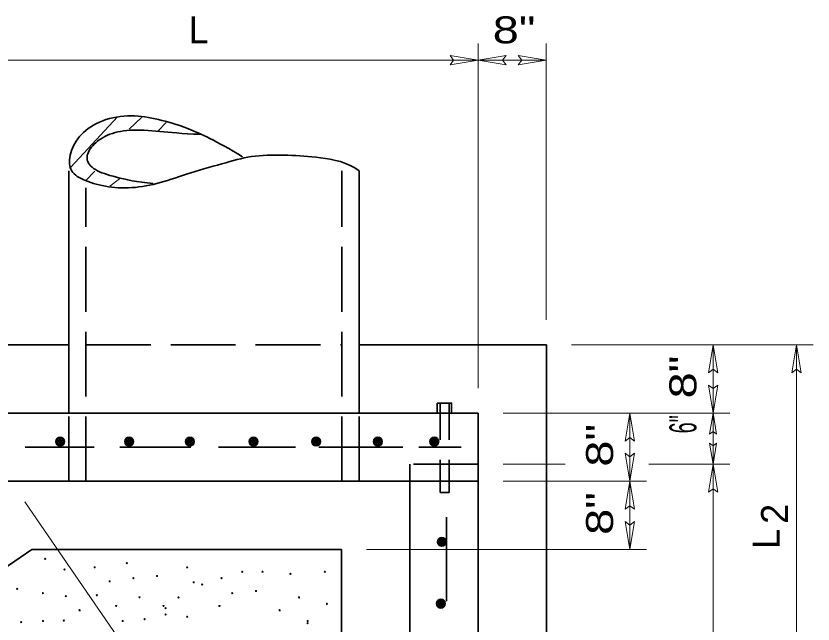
# Model space of a CAD drawing. Extents: x 178962.5 to 178977.5, y 178951.2 to 178972.9.
# Drawn here: x 178973.406 to 178977.392, y 178969.79 to 178972.831 of the extents above; entities that cross this region are included whole.
import ezdxf
from ezdxf.enums import TextEntityAlignment as Align

# ---------------------------------------------------------------- set-up
doc = ezdxf.new("R2010")
doc.units = 0
doc.header["$LTSCALE"] = 0.054
doc.linetypes.add('LONG_DASHED', pattern=[7.5, 6, -1.5])
doc.linetypes.add('MEDIUM_DASHED', pattern=[4.5, 3, -1.5])
for name, color, linetype, lineweight in [('1', 7, 'Continuous', 35), ('10', 7, 'Continuous', 13), ('12', 7, 'Continuous', 53), ('6', 7, 'Continuous', 13)]:
    doc.layers.add(name, color=color, linetype=linetype, lineweight=lineweight)

msp = doc.modelspace()

# ---------------------------------------------------------------- linework, layer by layer
at = {"layer": '1'}
for p, q in [((178973.67117, 178972.056), (178973.67117, 178970.8455)), ((178975.12183, 178972.056), (178975.12183, 178970.8455)), ((178972.56175, 178971.18683), (178973.67117, 178971.18683)), ((178976.05942, 178971.18683), (178975.12183, 178971.18683)), ((178976.05883, 178971.18683), (178976.05883, 178967.7735)), ((178975.51317, 178970.89517), (178975.51317, 178970.8455)), ((178975.528, 178970.8455), (178975.528, 178970.89517)), ((178975.57192, 178970.8455), (178975.57192, 178970.89517)), ((178975.7175, 178970.8455), (178972.9015, 178970.8455)), ((178975.7175, 178970.8455), (178975.7175, 178967.9015)), ((178973.63217, 178970.72417), (178973.60583, 178970.7005)), ((178973.62433, 178970.72442), (178973.60633, 178970.70842)), ((178973.638, 178970.72192), (178973.60725, 178970.6945)), ((178973.6425, 178970.71867), (178973.61008, 178970.68967)), ((178973.64592, 178970.71442), (178973.61383, 178970.68575)), ((178973.64833, 178970.70925), (178973.61875, 178970.68283)), ((178973.64933, 178970.70283), (178973.625, 178970.68117)), ((178973.64742, 178970.69375), (178973.63425, 178970.682)), ((178973.97683, 178970.72417), (178973.95033, 178970.7005)), ((178973.96892, 178970.72442), (178973.951, 178970.70842)), ((178973.98258, 178970.72192), (178973.95183, 178970.69458)), ((178973.98708, 178970.71875), (178973.95458, 178970.68975)), ((178973.99058, 178970.71442), (178973.9585, 178970.68575)), ((178973.993, 178970.70933), (178973.96342, 178970.68275)), ((178973.99392, 178970.70283), (178973.96958, 178970.68108)), ((178973.992, 178970.69375), (178973.97883, 178970.68208)), ((178974.28125, 178970.72417), (178974.25483, 178970.7005)), ((178974.27333, 178970.72442), (178974.25542, 178970.70842)), ((178974.287, 178970.72192), (178974.25625, 178970.69458)), ((178974.2915, 178970.71875), (178974.25908, 178970.68975)), ((178974.29492, 178970.71442), (178974.26283, 178970.68575)), ((178974.29733, 178970.70933), (178974.26775, 178970.68275)), ((178974.29833, 178970.70283), (178974.274, 178970.68108)), ((178974.29642, 178970.69375), (178974.28325, 178970.68208)), ((178974.59892, 178970.72417), (178974.5725, 178970.7005)), ((178974.59108, 178970.72442), (178974.57308, 178970.70842)), ((178974.60475, 178970.72192), (178974.574, 178970.69458)), ((178974.60917, 178970.71875), (178974.57675, 178970.68975)), ((178974.61275, 178970.71442), (178974.5805, 178970.68575)), ((178974.61517, 178970.70933), (178974.5855, 178970.68275)), ((178974.61608, 178970.70283), (178974.59175, 178970.68108)), ((178974.61417, 178970.69375), (178974.601, 178970.68208)), ((178974.91225, 178970.72417), (178974.88583, 178970.7005)), ((178974.90442, 178970.72442), (178974.8865, 178970.70842)), ((178974.91808, 178970.72192), (178974.88733, 178970.69458)), ((178974.9225, 178970.71875), (178974.89008, 178970.68975)), ((178974.92608, 178970.71442), (178974.89392, 178970.68575)), ((178974.9285, 178970.70933), (178974.89883, 178970.68275)), ((178974.92942, 178970.70283), (178974.90508, 178970.68108)), ((178974.9275, 178970.69375), (178974.91433, 178970.68208)), ((178975.22117, 178970.72417), (178975.19467, 178970.7005)), ((178975.21325, 178970.72442), (178975.19525, 178970.70842)), ((178975.22683, 178970.72192), (178975.19617, 178970.6945)), ((178975.23142, 178970.71867), (178975.19892, 178970.68967)), ((178975.23483, 178970.71442), (178975.20275, 178970.68575)), ((178975.23725, 178970.70925), (178975.20767, 178970.68283)), ((178975.23825, 178970.70283), (178975.21392, 178970.68117)), ((178975.23633, 178970.69375), (178975.22317, 178970.682)), ((178975.50308, 178970.72417), (178975.47658, 178970.7005)), ((178975.49525, 178970.72433), (178975.47725, 178970.70833)), ((178975.50892, 178970.722), (178975.47808, 178970.69458)), ((178975.51325, 178970.71867), (178975.48092, 178970.68967)), ((178975.51692, 178970.71442), (178975.48475, 178970.68575)), ((178975.51925, 178970.70933), (178975.48958, 178970.68275)), ((178975.52025, 178970.70283), (178975.49592, 178970.68117)), ((178975.51825, 178970.69375), (178975.50525, 178970.682)), ((178973.45217, 178970.67483), (178973.79675, 178970.67483)), ((178973.92658, 178970.67483), (178974.28017, 178970.67483)), ((178974.41883, 178970.67483), (178974.80383, 178970.67483)), ((178974.92017, 178970.67483), (178975.34083, 178970.67483)), ((178975.63217, 178970.67483), (178975.4215, 178970.67483)), ((178975.7175, 178970.50417), (178972.9015, 178970.50417)), ((178973.4135, 178970.50417), (178975.67483, 178970.50417)), ((178973.4135, 178970.50417), (178975.67483, 178970.50417)), ((178975.37617, 178970.50417), (178975.37617, 178967.9015)), ((178975.55917, 178969.90492), (178975.55917, 178970.32558)), ((178975.51983, 178970.21608), (178975.54883, 178970.18375)), ((178975.52408, 178970.21958), (178975.55275, 178970.18742)), ((178975.52917, 178970.222), (178975.55567, 178970.19242)), ((178975.53567, 178970.22292), (178975.55742, 178970.19867)), ((178975.54475, 178970.22108), (178975.5565, 178970.20792)), ((178975.51408, 178970.198), (178975.53008, 178970.18)), ((178975.51433, 178970.20583), (178975.538, 178970.17942)), ((178975.5165, 178970.21167), (178975.54392, 178970.18092)), ((178973.48525, 178970.16283), (178971.51783, 178968.81042)), ((178975.03483, 178970.16283), (178973.48525, 178970.16283)), ((178975.03483, 178970.16283), (178975.03483, 178967.7735)), ((178975.50983, 178969.89708), (178975.5335, 178969.87058)), ((178975.51217, 178969.90275), (178975.5395, 178969.87208)), ((178975.51542, 178969.90725), (178975.54442, 178969.87483)), ((178975.51967, 178969.91075), (178975.54825, 178969.87867)), ((178975.52475, 178969.91317), (178975.55125, 178969.8835)), ((178975.53117, 178969.91408), (178975.55292, 178969.88983)), ((178975.54025, 178969.91225), (178975.55208, 178969.89908)), ((178975.50967, 178969.88908), (178975.52567, 178969.87117))]:
    msp.add_line(p, q, dxfattribs=at)
at = {"layer": '1', "linetype": 'LONG_DASHED'}
for p, q in [((178975.0365, 178970.50417), (178975.0365, 178972.056)), ((178973.7565, 178970.50417), (178973.7565, 178971.97108)), ((178973.7565, 178971.18683), (178975.0365, 178971.18683)), ((178973.67117, 178970.50417), (178973.67117, 178970.8455)), ((178975.12183, 178970.50417), (178975.12183, 178970.8455)), ((178975.37617, 178970.5895), (178975.37617, 178970.50417)), ((178975.7175, 178970.5895), (178975.37617, 178970.5895))]:
    msp.add_line(p, q, dxfattribs=at)
at = {"layer": '1', "linetype": 'MEDIUM_DASHED'}
for p, q in [((178975.528, 178970.44883), (178975.528, 178970.8455)), ((178975.57192, 178970.44883), (178975.57192, 178970.8455)), ((178975.528, 178970.44883), (178975.57192, 178970.44883))]:
    msp.add_line(p, q, dxfattribs=at)
at = {"layer": '1'}
msp.add_lwpolyline([(178975.51317, 178970.89517), (178975.58492, 178970.89517), (178975.58492, 178970.8455)], dxfattribs=at)
for centre in [(178973.6275, 178970.70282), (178973.97208, 178970.70282), (178974.2765, 178970.70282), (178974.59425, 178970.70282), (178974.90758, 178970.70282), (178975.2164, 178970.70282), (178975.49838, 178970.70282), (178975.53569, 178970.20113), (178975.53125, 178969.89231)]:
    msp.add_circle(centre, 0.02184, dxfattribs=at)
for points in [[(178975.12183, 178972.056), (178975.06792, 178972.1005), (178974.91567, 178972.12733), (178974.7725, 178972.13625), (178974.5935, 178972.13625), (178974.46817, 178972.1005), (178974.27117, 178972.04708), (178974.128, 178971.9935), (178973.98475, 178971.96675), (178973.8505, 178971.97575), (178973.73408, 178972.01133), (178973.67117, 178972.056), (178973.6715, 178972.14508), (178973.72517, 178972.24317), (178973.83258, 178972.31458), (178973.98475, 178972.34133), (178974.11908, 178972.31458), (178974.25325, 178972.27892), (178974.4055, 178972.20758), (178974.53983, 178972.12733)], [(178974.0925, 178971.99375), (178974.01142, 178972.00025), (178973.89775, 178972.02608), (178973.79383, 178972.05842), (178973.74833, 178972.11675), (178973.78408, 178972.18458), (178973.85883, 178972.23958), (178973.96917, 178972.2655), (178974.125, 178972.25575), (178974.23217, 178972.24283), (178974.32958, 178972.23958)]]:
    msp.add_open_spline(points, degree=3, dxfattribs=at)
at = {"layer": '10'}
for p, q in [((178975.7175, 178972.69442), (178975.7175, 178970.9705)), ((178976.05842, 178972.69442), (178976.05842, 178971.31183)), ((178975.5775, 178972.63442), (178975.7175, 178972.61108)), ((178975.5775, 178972.63442), (178975.595, 178972.61108)), ((178975.5775, 178972.58775), (178975.7175, 178972.61108)), ((178975.5775, 178972.58775), (178975.595, 178972.61108)), ((178975.8575, 178972.63442), (178975.7175, 178972.61108)), ((178976.05842, 178972.61108), (178975.7175, 178972.61108)), ((178975.8575, 178972.58775), (178975.7175, 178972.61108)), ((178975.8575, 178972.63442), (178975.84, 178972.61108)), ((178975.8575, 178972.58775), (178975.84, 178972.61108)), ((178975.91842, 178972.63442), (178976.05842, 178972.61108)), ((178975.91842, 178972.63442), (178975.93592, 178972.61108)), ((178975.91842, 178972.58775), (178976.05842, 178972.61108)), ((178975.91842, 178972.58775), (178975.93592, 178972.61108)), ((178976.18442, 178971.18683), (178977.39233, 178971.18683)), ((178976.869, 178971.04683), (178976.89233, 178971.18683)), ((178976.89233, 178971.18683), (178976.89233, 178970.8455)), ((178976.91567, 178971.04683), (178976.89233, 178971.18683)), ((178977.28567, 178971.04683), (178977.309, 178971.18683)), ((178977.309, 178971.18683), (178977.309, 178969.39308)), ((178977.33233, 178971.04683), (178977.309, 178971.18683)), ((178976.869, 178971.04683), (178976.89233, 178971.06433)), ((178976.91567, 178971.04683), (178976.89233, 178971.06433)), ((178977.28567, 178971.04683), (178977.309, 178971.06433)), ((178977.33233, 178971.04683), (178977.309, 178971.06433)), ((178976.869, 178970.9855), (178976.89233, 178970.8455)), ((178976.869, 178970.9855), (178976.89233, 178970.968)), ((178976.91567, 178970.9855), (178976.89233, 178970.8455)), ((178976.91567, 178970.9855), (178976.89233, 178970.968)), ((178976.97567, 178970.8455), (178975.8425, 178970.8455)), ((178976.45233, 178970.7055), (178976.47567, 178970.8455)), ((178976.47567, 178970.8455), (178976.47567, 178970.50417)), ((178976.499, 178970.7055), (178976.47567, 178970.8455)), ((178976.87483, 178970.7405), (178976.89233, 178970.8455)), ((178976.89233, 178970.8455), (178976.89233, 178970.5895)), ((178976.90983, 178970.7405), (178976.89233, 178970.8455)), ((178976.87483, 178970.7405), (178976.89233, 178970.75367)), ((178976.90983, 178970.7405), (178976.89233, 178970.75367)), ((178976.45233, 178970.7055), (178976.47567, 178970.723)), ((178976.499, 178970.7055), (178976.47567, 178970.723)), ((178976.87483, 178970.6945), (178976.89233, 178970.5895)), ((178976.87483, 178970.6945), (178976.89233, 178970.68133)), ((178976.90983, 178970.6945), (178976.89233, 178970.5895)), ((178976.90983, 178970.6945), (178976.89233, 178970.68133)), ((178976.45233, 178970.64417), (178976.47567, 178970.50417)), ((178976.45233, 178970.64417), (178976.47567, 178970.62667)), ((178976.499, 178970.64417), (178976.47567, 178970.50417)), ((178976.499, 178970.64417), (178976.47567, 178970.62667)), ((178975.8425, 178970.5895), (178976.15225, 178970.5895)), ((178976.57067, 178970.5895), (178976.97567, 178970.5895)), ((178976.869, 178970.4495), (178976.89233, 178970.5895)), ((178976.89233, 178967.7735), (178976.89233, 178970.5895)), ((178976.91567, 178970.4495), (178976.89233, 178970.5895)), ((178975.8425, 178970.50417), (178976.559, 178970.50417)), ((178976.45233, 178970.36417), (178976.47567, 178970.50417)), ((178976.47567, 178970.50417), (178976.47567, 178970.16283)), ((178976.499, 178970.36417), (178976.47567, 178970.50417)), ((178976.869, 178970.4495), (178976.89233, 178970.467)), ((178976.91567, 178970.4495), (178976.89233, 178970.467)), ((178973.45008, 178970.40117), (178974.35142, 178969.09)), ((178976.45233, 178970.36417), (178976.47567, 178970.38167)), ((178976.499, 178970.36417), (178976.47567, 178970.38167)), ((178976.45233, 178970.30283), (178976.47567, 178970.16283)), ((178976.45233, 178970.30283), (178976.47567, 178970.28533)), ((178976.499, 178970.30283), (178976.47567, 178970.16283)), ((178976.499, 178970.30283), (178976.47567, 178970.28533)), ((178975.15983, 178970.16283), (178976.559, 178970.16283))]:
    msp.add_line(p, q, dxfattribs=at)
msp.add_lwpolyline([(178972.56175, 178972.61108), (178972.90308, 178972.61108), (178975.7175, 178972.61108)], dxfattribs=at)
at = {"layer": '6'}
for p, q in [((178973.91392, 178972.327), (178973.68017, 178972.07467)), ((178974.03408, 178972.32375), (178973.97242, 178972.2655)), ((178974.1575, 178972.29783), (178974.11525, 178972.25575)), ((178973.80033, 178972.05517), (178973.75483, 178972.00667)), ((178973.92367, 178972.01642), (178973.875, 178971.98075))]:
    msp.add_line(p, q, dxfattribs=at)
for centre in [(178973.55237, 178970.11654), (178973.96121, 178970.09504), (178973.64921, 178970.06288), (178973.79979, 178970.07362), (178974.26246, 178970.07362), (178973.99346, 178970.02004), (178974.11179, 178970.03079), (178974.43454, 178970.02004), (178974.53836, 178970.05111), (178974.63896, 178970.05221), (178974.77879, 178970.04146), (178974.95096, 178970.05221), (178973.87528, 178970.00394), (178974.29471, 178969.99863), (178974.33771, 178969.98787), (178973.41254, 178969.96646), (178973.54162, 178969.94504), (178973.81054, 178969.93429), (178974.48837, 178969.94504), (178974.60671, 178969.95571), (178973.65553, 178969.93019), (178974.02411, 178969.92394), (178974.21937, 178969.92354), (178974.82187, 178969.92354), (178973.72454, 178969.85929), (178973.90737, 178969.88071), (178974.14404, 178969.88071), (178974.15488, 178969.86996), (178974.42379, 178969.88071), (178974.72504, 178969.85929), (178974.96171, 178969.89138), (178974.04969, 178969.81452), (178974.15488, 178969.83779), (178974.26246, 178969.82712), (178973.43261, 178969.80009), (178973.54162, 178969.80571), (178973.64594, 178969.80761), (178973.93971, 178969.80563), (178974.86487, 178969.80571), (178974.86487, 178969.79496)]:
    msp.add_circle(centre, 0.00298, dxfattribs=at)

# ---------------------------------------------------------------- texts
at = {"layer": '12'}
msp.add_text('L', height=0.135, dxfattribs=at).set_placement((178974.31971, 178972.69442), align=Align.CENTER)
at = {"layer": '12', "width": 1.3}
msp.add_text('8"', height=0.135, dxfattribs=at).set_placement((178975.89738, 178972.69442), align=Align.CENTER)
at = {"layer": '12'}
for s, width, p in [('8"', 1.3, (178976.80892, 178971.02567)), ('6"', 0.55, (178976.809, 178970.78921)), ('8"', 1.3, (178976.39225, 178970.68433)), ('8"', 1.3, (178976.39225, 178970.343))]:
    msp.add_text(s, height=0.135, rotation=90, dxfattribs=dict(at, width=width)).set_placement(p, align=Align.CENTER)
for s, p in [('2', (178977.26725, 178970.34112)), ('L', (178977.22558, 178970.21612))]:
    msp.add_text(s, height=0.135, rotation=90, dxfattribs=at).set_placement(p, align=Align.CENTER)

doc.saveas('drawing.dxf')
